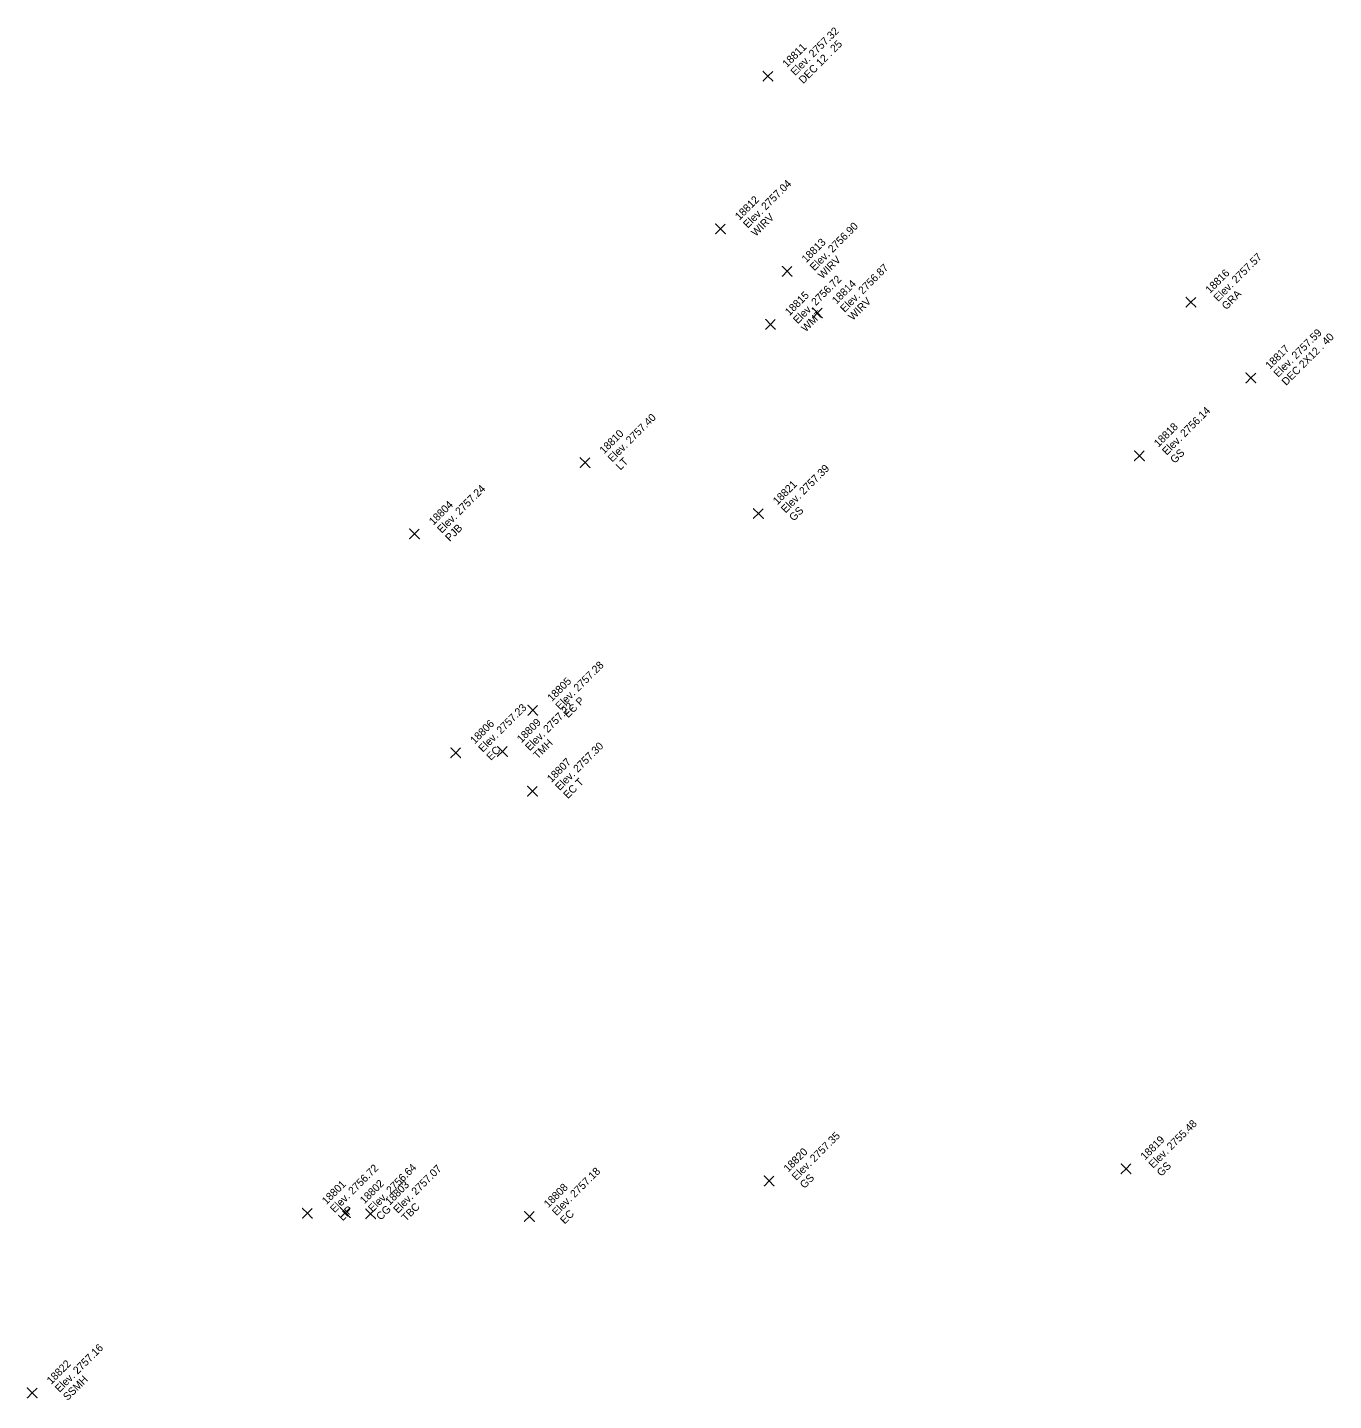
# Model space of a CAD drawing. Extents: x 2493999 to 2503109, y 700767 to 706646.
# Drawn here: x 2502296.64 to 2502337.45, y 700767.31 to 700810.23 of the extents above; entities that cross this region are included whole.
import ezdxf

# ---------------------------------------------------------------- set-up
doc = ezdxf.new("R2010")
doc.units = 0
doc.layers.add('ALG_CL_BLUE_Horiz', color=7, linetype='Continuous')
doc.layers.add('DES_SURFACE_Existing-Ground', color=7, linetype='Continuous')

msp = doc.modelspace()

# ---------------------------------------------------------------- linework, layer by layer
at = {"layer": 'ALG_CL_BLUE_Horiz'}
for points in [[(2502319.781, 700808.711), (2502319.631, 700808.861), (2502319.781, 700808.711), (2502319.631, 700808.561), (2502319.781, 700808.711), (2502319.931, 700808.561), (2502319.781, 700808.711), (2502319.931, 700808.861)], [(2502318.297, 700803.939), (2502318.147, 700804.089), (2502318.297, 700803.939), (2502318.147, 700803.789), (2502318.297, 700803.939), (2502318.447, 700803.789), (2502318.297, 700803.939), (2502318.447, 700804.089)], [(2502320.381, 700802.611), (2502320.231, 700802.761), (2502320.381, 700802.611), (2502320.231, 700802.461), (2502320.381, 700802.611), (2502320.531, 700802.461), (2502320.381, 700802.611), (2502320.531, 700802.761)], [(2502332.998, 700801.647), (2502332.848, 700801.797), (2502332.998, 700801.647), (2502332.848, 700801.497), (2502332.998, 700801.647), (2502333.148, 700801.497), (2502332.998, 700801.647), (2502333.148, 700801.797)], [(2502319.859, 700800.953), (2502319.709, 700801.103), (2502319.859, 700800.953), (2502319.709, 700800.803), (2502319.859, 700800.953), (2502320.009, 700800.803), (2502319.859, 700800.953), (2502320.009, 700801.103)], [(2502321.328, 700801.312), (2502321.178, 700801.462), (2502321.328, 700801.312), (2502321.178, 700801.162), (2502321.328, 700801.312), (2502321.478, 700801.162), (2502321.328, 700801.312), (2502321.478, 700801.462)], [(2502334.869, 700799.28), (2502334.719, 700799.43), (2502334.869, 700799.28), (2502334.719, 700799.13), (2502334.869, 700799.28), (2502335.019, 700799.13), (2502334.869, 700799.28), (2502335.019, 700799.43)], [(2502331.388, 700796.845), (2502331.238, 700796.995), (2502331.388, 700796.845), (2502331.238, 700796.695), (2502331.388, 700796.845), (2502331.538, 700796.695), (2502331.388, 700796.845), (2502331.538, 700796.995)], [(2502314.066, 700796.631), (2502313.916, 700796.781), (2502314.066, 700796.631), (2502313.916, 700796.481), (2502314.066, 700796.631), (2502314.216, 700796.481), (2502314.066, 700796.631), (2502314.216, 700796.781)], [(2502319.482, 700795.041), (2502319.332, 700795.191), (2502319.482, 700795.041), (2502319.332, 700794.891), (2502319.482, 700795.041), (2502319.632, 700794.891), (2502319.482, 700795.041), (2502319.632, 700795.191)], [(2502308.735, 700794.406), (2502308.585, 700794.556), (2502308.735, 700794.406), (2502308.585, 700794.256), (2502308.735, 700794.406), (2502308.885, 700794.256), (2502308.735, 700794.406), (2502308.885, 700794.556)], [(2502312.433, 700788.891), (2502312.283, 700789.041), (2502312.433, 700788.891), (2502312.283, 700788.741), (2502312.433, 700788.891), (2502312.583, 700788.741), (2502312.433, 700788.891), (2502312.583, 700789.041)], [(2502310.023, 700787.563), (2502309.873, 700787.713), (2502310.023, 700787.563), (2502309.873, 700787.413), (2502310.023, 700787.563), (2502310.173, 700787.413), (2502310.023, 700787.563), (2502310.173, 700787.713)], [(2502311.484, 700787.605), (2502311.334, 700787.755), (2502311.484, 700787.605), (2502311.334, 700787.455), (2502311.484, 700787.605), (2502311.634, 700787.455), (2502311.484, 700787.605), (2502311.634, 700787.755)], [(2502312.423, 700786.362), (2502312.273, 700786.512), (2502312.423, 700786.362), (2502312.273, 700786.212), (2502312.423, 700786.362), (2502312.573, 700786.212), (2502312.423, 700786.362), (2502312.573, 700786.512)], [(2502330.968, 700774.559), (2502330.818, 700774.709), (2502330.968, 700774.559), (2502330.818, 700774.409), (2502330.968, 700774.559), (2502331.118, 700774.409), (2502330.968, 700774.559), (2502331.118, 700774.709)], [(2502319.817, 700774.18), (2502319.667, 700774.33), (2502319.817, 700774.18), (2502319.667, 700774.03), (2502319.817, 700774.18), (2502319.967, 700774.03), (2502319.817, 700774.18), (2502319.967, 700774.33)], [(2502305.391, 700773.168), (2502305.241, 700773.318), (2502305.391, 700773.168), (2502305.241, 700773.018), (2502305.391, 700773.168), (2502305.541, 700773.018), (2502305.391, 700773.168), (2502305.541, 700773.318)], [(2502306.579, 700773.188), (2502306.429, 700773.338), (2502306.579, 700773.188), (2502306.429, 700773.038), (2502306.579, 700773.188), (2502306.729, 700773.038), (2502306.579, 700773.188), (2502306.729, 700773.338)], [(2502307.366, 700773.15), (2502307.216, 700773.3), (2502307.366, 700773.15), (2502307.216, 700773), (2502307.366, 700773.15), (2502307.516, 700773), (2502307.366, 700773.15), (2502307.516, 700773.3)], [(2502312.326, 700773.07), (2502312.176, 700773.22), (2502312.326, 700773.07), (2502312.176, 700772.92), (2502312.326, 700773.07), (2502312.476, 700772.92), (2502312.326, 700773.07), (2502312.476, 700773.22)], [(2502296.793, 700767.552), (2502296.643, 700767.702), (2502296.793, 700767.552), (2502296.643, 700767.402), (2502296.793, 700767.552), (2502296.943, 700767.402), (2502296.793, 700767.552), (2502296.943, 700767.702)]]:
    msp.add_lwpolyline(points, dxfattribs=at)

# ---------------------------------------------------------------- texts
at = {"layer": 'DES_SURFACE_Existing-Ground'}
for s, p in [('Elev. 2757.32', (2502320.63, 700808.711)), ('18811', (2502320.375, 700808.966)), ('DEC 12 . 25', (2502320.884, 700808.456)), ('Elev. 2757.04', (2502319.146, 700803.939)), ('18812', (2502318.891, 700804.194)), ('WIRV', (2502319.4, 700803.684)), ('Elev. 2756.90', (2502321.23, 700802.611)), ('18813', (2502320.975, 700802.866)), ('WIRV', (2502321.484, 700802.356)), ('Elev. 2756.87', (2502322.177, 700801.312)), ('Elev. 2757.57', (2502333.847, 700801.647)), ('Elev. 2756.72', (2502320.708, 700800.953)), ('18816', (2502333.592, 700801.902)), ('18815', (2502320.453, 700801.208)), ('18814', (2502321.922, 700801.567)), ('GRA', (2502334.101, 700801.392)), ('WIRV', (2502322.431, 700801.057)), ('WMT', (2502320.962, 700800.698)), ('Elev. 2757.59', (2502335.718, 700799.28)), ('DEC 2X12 . 40', (2502335.972, 700799.025)), ('18817', (2502335.463, 700799.535)), ('Elev. 2757.40', (2502314.915, 700796.631)), ('Elev. 2756.14', (2502332.237, 700796.845)), ('18818', (2502331.982, 700797.1)), ('18810', (2502314.66, 700796.886)), ('LT', (2502315.169, 700796.376)), ('GS', (2502332.491, 700796.59)), ('Elev. 2757.39', (2502320.331, 700795.041)), ('18821', (2502320.076, 700795.296)), ('Elev. 2757.24', (2502309.584, 700794.406)), ('18804', (2502309.329, 700794.661)), ('GS', (2502320.585, 700794.786)), ('PJB', (2502309.838, 700794.151)), ('Elev. 2757.28', (2502313.282, 700788.891)), ('18805', (2502313.027, 700789.146)), ('Elev. 2757.23', (2502310.872, 700787.563)), ('Elev. 2757.22', (2502312.333, 700787.605)), ('EC P', (2502313.536, 700788.636)), ('18806', (2502310.617, 700787.818)), ('18809', (2502312.078, 700787.86)), ('TMH', (2502312.587, 700787.35)), ('Elev. 2757.30', (2502313.272, 700786.362)), ('EC', (2502311.126, 700787.308)), ('18807', (2502313.017, 700786.617)), ('EC T', (2502313.526, 700786.107)), ('Elev. 2755.48', (2502331.817, 700774.559)), ('Elev. 2757.35', (2502320.666, 700774.18)), ('18819', (2502331.562, 700774.814)), ('18820', (2502320.411, 700774.435)), ('Elev. 2756.72', (2502306.24, 700773.168)), ('Elev. 2756.64', (2502307.428, 700773.188)), ('Elev. 2757.07', (2502308.215, 700773.15)), ('Elev. 2757.18', (2502313.175, 700773.07)), ('GS', (2502332.071, 700774.304)), ('18801', (2502305.985, 700773.423)), ('18802', (2502307.173, 700773.443)), ('18803', (2502307.96, 700773.405)), ('18808', (2502312.92, 700773.325)), ('GS', (2502320.92, 700773.925)), ('LIP', (2502306.494, 700772.913)), ('CG', (2502307.682, 700772.933)), ('TBC', (2502308.469, 700772.895)), ('EC', (2502313.429, 700772.815)), ('Elev. 2757.16', (2502297.642, 700767.552)), ('18822', (2502297.387, 700767.807)), ('SSMH', (2502297.896, 700767.297))]:
    msp.add_text(s, height=0.24, rotation=45, dxfattribs=at).set_placement(p)

doc.saveas('drawing.dxf')
